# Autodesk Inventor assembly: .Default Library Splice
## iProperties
ParentFileIdentifier: 5|1|0|0|108|1|0|0|80|0|65|0|84|0|72|0|83|0|59|0|67|0|58|0|92|0|86|0|97|0|117|0|108|0|116|0|32|0|87|0|111|0|114|0|107|0|115|0|112|0|97|0|99|0|101|0|92|0|69|0|110
Part Number: .Default Library Splice
Material: Default
Description: Default Library Splice
Created: 2009-02
Part Number: 100500.Harness1
Document SubType Name: Assembly
Designer: Autodesk
HarnessSettings: <HarnessSettings><Defaults><Segments><Diameter value="0.200 in" fromwires="True"/><Offset value="0.100 in"/><ColorStyle value="Blue"/><RoundUp value=""/><BendRa
Author: Autodesk
